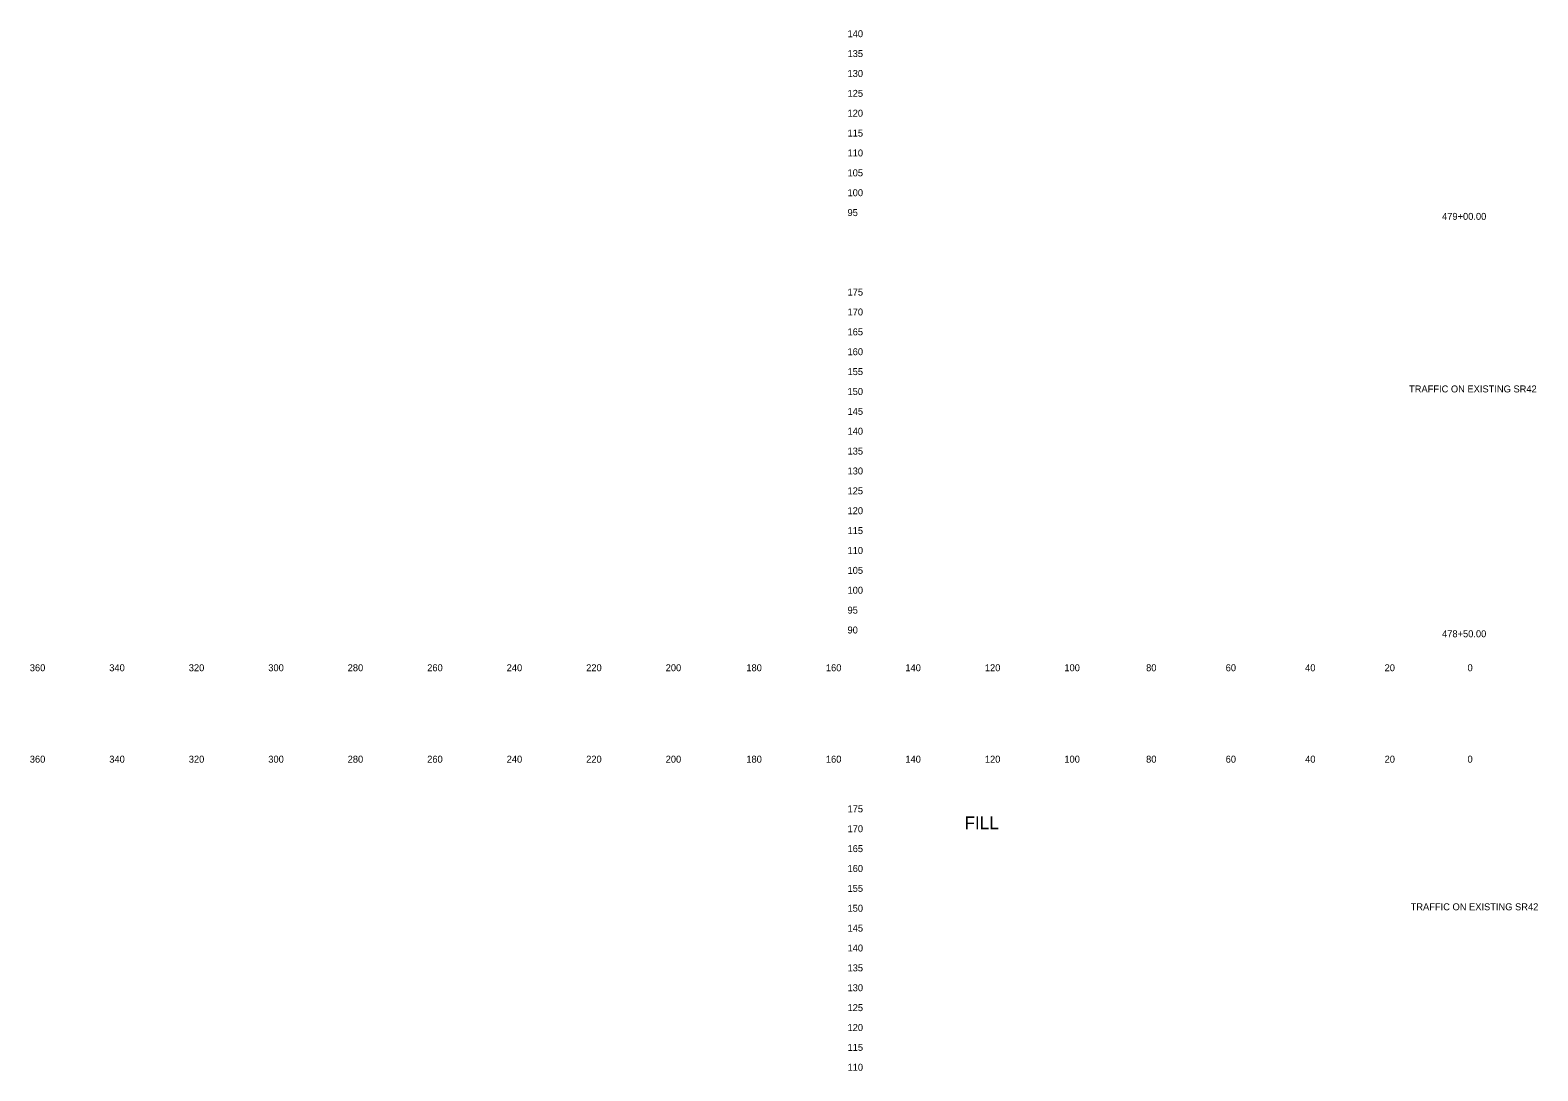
# Model space of a CAD drawing. Extents: x 21281 to 22024, y 6472 to 15198.
# Drawn here: x 21280.5 to 21659.8, y 11664.8 to 11926.6 of the extents above; entities that cross this region are included whole.
import ezdxf

# ---------------------------------------------------------------- set-up
doc = ezdxf.new("R2010")
doc.units = 0
for name, color, linetype in [('XS_SHEET_LABELS_ELEVATION', 7, 'Continuous'), ('XS_SHEET_LABELS_OFFSET', 7, 'Continuous'), ('XS_SHEET_LABELS_STATION', 7, 'Continuous')]:
    doc.layers.add(name, color=color, linetype=linetype)

msp = doc.modelspace()

# ---------------------------------------------------------------- texts
at = {"layer": 'XS_SHEET_LABELS_ELEVATION'}
for s, p in [('  140  ', (21484.84, 11924.84)), ('  135  ', (21484.84, 11919.84)), ('  130  ', (21484.84, 11914.84)), ('  125  ', (21484.84, 11909.84)), ('  120  ', (21484.84, 11904.84)), ('  115  ', (21484.84, 11899.84)), ('  110  ', (21484.84, 11894.84)), ('  105  ', (21484.84, 11889.84)), ('  100  ', (21484.84, 11884.84)), ('  95  ', (21484.84, 11879.84)), ('  175  ', (21484.84, 11859.84)), ('  170  ', (21484.84, 11854.84)), ('  165  ', (21484.84, 11849.84)), ('  160  ', (21484.84, 11844.84)), ('  155  ', (21484.84, 11839.84)), ('  150  ', (21484.84, 11834.84)), ('  145  ', (21484.84, 11829.84)), ('  140  ', (21484.84, 11824.84)), ('  135  ', (21484.84, 11819.84)), ('  130  ', (21484.84, 11814.84)), ('  125  ', (21484.84, 11809.84)), ('  120  ', (21484.84, 11804.84)), ('  115  ', (21484.84, 11799.84)), ('  110  ', (21484.84, 11794.84)), ('  105  ', (21484.84, 11789.84)), ('  100  ', (21484.84, 11784.84)), ('  95  ', (21484.84, 11779.84)), ('  90  ', (21484.84, 11774.84)), ('  175  ', (21484.84, 11729.84)), ('  170  ', (21484.84, 11724.84)), ('  165  ', (21484.84, 11719.84)), ('  160  ', (21484.84, 11714.84)), ('  155  ', (21484.84, 11709.84)), ('  150  ', (21484.84, 11704.84)), ('  145  ', (21484.84, 11699.84)), ('  140  ', (21484.84, 11694.84)), ('  135  ', (21484.84, 11689.84)), ('  130  ', (21484.84, 11684.84)), ('  125  ', (21484.84, 11679.84)), ('  120  ', (21484.84, 11674.84)), ('  115  ', (21484.84, 11669.84)), ('  110  ', (21484.84, 11664.84))]:
    msp.add_text(s, height=1.75, dxfattribs=at).set_placement(p)
at = {"layer": 'XS_SHEET_LABELS_OFFSET'}
for s, height, p in [('  360  ', 1.75, (21279.14, 11765.34)), ('  340  ', 1.75, (21299.13, 11765.34)), ('  320  ', 1.75, (21319.13, 11765.34)), ('  300  ', 1.75, (21339.13, 11765.34)), ('  280  ', 1.75, (21359.1, 11765.34)), ('  260  ', 1.75, (21379.11, 11765.34)), ('  240  ', 1.75, (21399.1, 11765.34)), ('  220  ', 1.75, (21419.1, 11765.34)), ('  200  ', 1.75, (21439.1, 11765.34)), ('  180  ', 1.75, (21459.39, 11765.34)), ('  160  ', 1.75, (21479.4, 11765.34)), ('  140  ', 1.75, (21499.39, 11765.34)), ('  120  ', 1.75, (21519.39, 11765.34)), ('  100  ', 1.75, (21539.39, 11765.34)), ('  80  ', 1.75, (21559.95, 11765.34)), ('  60  ', 1.75, (21579.97, 11765.34)), ('  40  ', 1.75, (21599.95, 11765.34)), ('  20  ', 1.75, (21619.95, 11765.34)), ('  0  ', 1.75, (21640.81, 11765.34)), ('  0  ', 1.75, (21640.81, 11765.34)), ('  360  ', 1.75, (21279.14, 11742.34)), ('  340  ', 1.75, (21299.13, 11742.34)), ('  320  ', 1.75, (21319.13, 11742.34)), ('  300  ', 1.75, (21339.13, 11742.34)), ('  280  ', 1.75, (21359.1, 11742.34)), ('  260  ', 1.75, (21379.11, 11742.34)), ('  240  ', 1.75, (21399.1, 11742.34)), ('  220  ', 1.75, (21419.1, 11742.34)), ('  200  ', 1.75, (21439.1, 11742.34)), ('  180  ', 1.75, (21459.39, 11742.34)), ('  160  ', 1.75, (21479.4, 11742.34)), ('  140  ', 1.75, (21499.39, 11742.34)), ('  120  ', 1.75, (21519.39, 11742.34)), ('  100  ', 1.75, (21539.39, 11742.34)), ('  80  ', 1.75, (21559.95, 11742.34)), ('  60  ', 1.75, (21579.97, 11742.34)), ('  40  ', 1.75, (21599.95, 11742.34)), ('  20  ', 1.75, (21619.95, 11742.34)), ('  0  ', 1.75, (21640.81, 11742.34)), ('  0  ', 1.75, (21640.81, 11742.34)), ('FILL', 3.222, (21515.57, 11725.59))]:
    msp.add_text(s, height=height, dxfattribs=at).set_placement(p)
at = {"layer": 'XS_SHEET_LABELS_STATION'}
for s, p in [('  479+00.00  ', (21634.4, 11878.89)), ('TRAFFIC ON EXISTING SR42', (21627.4, 11835.48)), ('  478+50.00  ', (21634.4, 11773.89)), ('TRAFFIC ON EXISTING SR42', (21627.8, 11705.2))]:
    msp.add_text(s, height=1.75, dxfattribs=at).set_placement(p)

doc.saveas('drawing.dxf')
